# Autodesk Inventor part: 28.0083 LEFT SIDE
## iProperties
Created: 2006-12
Part Number: 28.0083 LEFT SIDE
Document SubType Name: Modeling
Designer: Andy Moles
Material: Aluminum-6061
Density: 2.71 g/cm^3
Author: Andy Moles
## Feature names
1. Extrusion1
2. Extrusion2
3. Extrusion3
4. Extrusion4
5. Extrusion5
6. Hole1
7. Mirror1
8. Hole4
9. Hole5
10. Extrusion6
11. Chamfer1
